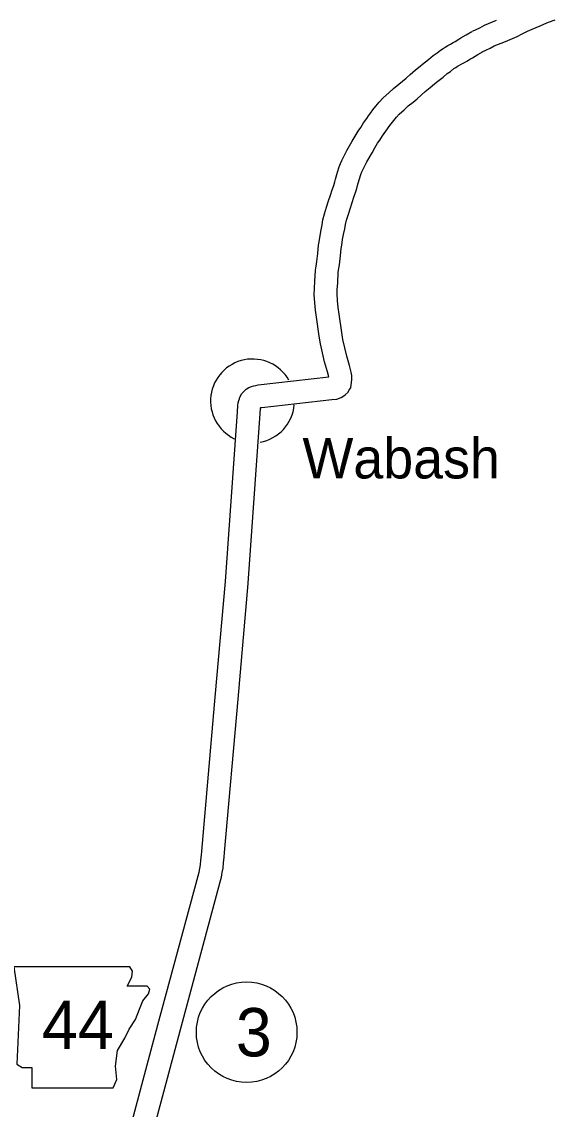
# Model space of a CAD drawing. Extents: x -939622 to -934222, y 1383701 to 1385301.
# Drawn here: x -935804.2 to -935783.2, y 1383947.05 to 1383989.81 of the extents above; entities that cross this region are included whole.
import ezdxf

# ---------------------------------------------------------------- set-up
doc = ezdxf.new("R2010")
doc.units = 0
for name, color, linetype in [('Level 10', 7, 'Continuous'), ('Level 21', 7, 'Continuous'), ('Level 24', 7, 'Continuous'), ('Level 27', 7, 'Continuous')]:
    doc.layers.add(name, color=color, linetype=linetype)

msp = doc.modelspace()

# ---------------------------------------------------------------- linework, layer by layer
at = {"layer": 'Level 10'}
for points in [[(-935786.454, 1383989.444), (-935786.314, 1383989.51), (-935786.172, 1383989.575), (-935785.991, 1383989.674), (-935785.512, 1383989.871)], [(-935786.07, 1383988.63), (-935785.935, 1383988.693), (-935785.767, 1383988.77), (-935785.602, 1383988.861), (-935785.163, 1383989.042), (-935784.702, 1383989.24), (-935784.503, 1383989.334), (-935784.287, 1383989.437), (-935784.111, 1383989.524), (-935783.945, 1383989.587), (-935783.799, 1383989.648), (-935783.644, 1383989.717), (-935783.472, 1383989.792), (-935783.199, 1383989.894)], [(-935796.182, 1383967.795), (-935795.712, 1383974.47), (-935795.698, 1383974.717), (-935795.674, 1383974.831), (-935795.655, 1383974.923), (-935795.631, 1383974.983), (-935795.613, 1383975.051), (-935795.538, 1383975.196), (-935795.456, 1383975.279), (-935795.367, 1383975.371), (-935795.256, 1383975.429), (-935795.151, 1383975.476), (-935795.07, 1383975.492), (-935794.991, 1383975.515), (-935794.889, 1383975.534), (-935792.117, 1383975.851), (-935792.17, 1383976.046), (-935792.282, 1383976.434), (-935792.439, 1383977.144), (-935792.493, 1383977.45), (-935792.595, 1383978.193), (-935792.632, 1383978.476), (-935792.663, 1383978.763), (-935792.69, 1383979.089), (-935792.682, 1383979.317), (-935792.661, 1383979.607), (-935792.638, 1383980.047), (-935792.614, 1383980.197), (-935792.582, 1383980.379), (-935792.551, 1383980.695), (-935792.517, 1383981.024), (-935792.493, 1383981.165), (-935792.459, 1383981.407), (-935792.414, 1383981.631), (-935792.373, 1383981.832), (-935792.343, 1383982.021), (-935792.283, 1383982.261), (-935792.198, 1383982.519), (-935792.123, 1383982.765), (-935792.048, 1383982.996), (-935791.975, 1383983.21), (-935791.919, 1383983.375), (-935791.875, 1383983.519), (-935791.843, 1383983.625), (-935791.821, 1383983.709), (-935791.768, 1383983.892), (-935791.701, 1383984.102), (-935791.648, 1383984.239), (-935791.6, 1383984.358), (-935791.473, 1383984.613), (-935791.404, 1383984.744), (-935791.187, 1383985.118), (-935791.072, 1383985.312), (-935790.953, 1383985.515), (-935790.858, 1383985.654), (-935790.742, 1383985.832), (-935790.618, 1383986.011), (-935790.546, 1383986.12), (-935790.474, 1383986.218), (-935790.374, 1383986.352), (-935790.259, 1383986.496), (-935790.137, 1383986.647), (-935789.976, 1383986.823), (-935789.752, 1383987.023), (-935789.572, 1383987.186), (-935789.363, 1383987.356), (-935789.208, 1383987.48), (-935789.072, 1383987.597), (-935788.913, 1383987.745), (-935788.703, 1383987.921), (-935788.522, 1383988.07), (-935788.425, 1383988.149), (-935788.31, 1383988.232), (-935788.188, 1383988.326), (-935788.004, 1383988.488), (-935787.854, 1383988.588), (-935787.723, 1383988.694), (-935787.615, 1383988.766), (-935787.537, 1383988.82), (-935787.428, 1383988.886), (-935787.32, 1383988.938), (-935787.222, 1383988.994), (-935787.139, 1383989.043), (-935786.997, 1383989.13), (-935786.913, 1383989.178), (-935786.7, 1383989.303), (-935786.488, 1383989.426)], [(-935795.284, 1383967.732), (-935794.814, 1383974.412), (-935794.803, 1383974.598), (-935794.796, 1383974.635), (-935794.782, 1383974.638), (-935794.752, 1383974.644), (-935791.998, 1383974.959), (-935791.798, 1383974.976), (-935791.624, 1383975.032), (-935791.519, 1383975.1), (-935791.464, 1383975.146), (-935791.346, 1383975.251), (-935791.306, 1383975.332), (-935791.244, 1383975.423), (-935791.202, 1383975.742), (-935791.208, 1383975.812), (-935791.209, 1383975.902), (-935791.232, 1383976.028), (-935791.303, 1383976.289), (-935791.409, 1383976.656), (-935791.556, 1383977.32), (-935791.604, 1383977.59), (-935791.703, 1383978.313), (-935791.738, 1383978.582), (-935791.767, 1383978.848), (-935791.789, 1383979.11), (-935791.783, 1383979.268), (-935791.763, 1383979.55), (-935791.741, 1383979.952), (-935791.726, 1383980.049), (-935791.69, 1383980.259), (-935791.656, 1383980.605), (-935791.625, 1383980.902), (-935791.604, 1383981.026), (-935791.572, 1383981.254), (-935791.532, 1383981.453), (-935791.487, 1383981.673), (-935791.461, 1383981.84), (-935791.418, 1383982.01), (-935791.34, 1383982.247), (-935791.265, 1383982.495), (-935791.195, 1383982.711), (-935791.123, 1383982.92), (-935791.062, 1383983.099), (-935791.014, 1383983.257), (-935790.977, 1383983.38), (-935790.953, 1383983.471), (-935790.907, 1383983.632), (-935790.852, 1383983.803), (-935790.812, 1383983.907), (-935790.779, 1383983.987), (-935790.671, 1383984.204), (-935790.616, 1383984.309), (-935790.411, 1383984.662), (-935790.296, 1383984.855), (-935790.191, 1383985.034), (-935790.109, 1383985.155), (-935789.995, 1383985.329), (-935789.872, 1383985.507), (-935789.808, 1383985.605), (-935789.75, 1383985.682), (-935789.661, 1383985.803), (-935789.557, 1383985.932), (-935789.454, 1383986.06), (-935789.343, 1383986.182), (-935789.151, 1383986.354), (-935788.987, 1383986.502), (-935788.798, 1383986.655), (-935788.633, 1383986.787), (-935788.472, 1383986.926), (-935788.316, 1383987.07), (-935788.128, 1383987.229), (-935787.952, 1383987.373), (-935787.877, 1383987.434), (-935787.773, 1383987.51), (-935787.615, 1383987.63), (-935787.454, 1383987.772), (-935787.319, 1383987.862), (-935787.188, 1383987.969), (-935787.112, 1383988.02), (-935787.048, 1383988.064), (-935786.996, 1383988.095), (-935786.901, 1383988.142), (-935786.773, 1383988.215), (-935786.677, 1383988.27), (-935786.539, 1383988.355), (-935786.462, 1383988.399), (-935786.246, 1383988.525), (-935786.036, 1383988.648)], [(-935804.586, 1383930.251), (-935804.322, 1383931.164), (-935802.411, 1383938.033), (-935802.345, 1383938.267), (-935802.303, 1383938.38), (-935802.256, 1383938.476), (-935802.14, 1383938.625), (-935801.955, 1383938.727), (-935801.946, 1383938.73), (-935801.756, 1383939.445), (-935798.837, 1383950.366), (-935797.258, 1383956.223), (-935797.22, 1383956.373), (-935797.191, 1383956.516), (-935797.167, 1383956.654), (-935797.146, 1383956.842), (-935797.123, 1383957.04), (-935797.115, 1383957.202), (-935796.58, 1383963.255), (-935796.181, 1383967.803)], [(-935803.642, 1383930.27), (-935803.392, 1383931.149), (-935801.544, 1383937.791), (-935801.512, 1383937.906), (-935801.32, 1383938.046), (-935801.244, 1383938.136), (-935801.201, 1383938.196), (-935801.118, 1383938.341), (-935800.886, 1383939.212), (-935797.967, 1383950.133), (-935796.387, 1383955.995), (-935796.342, 1383956.173), (-935796.306, 1383956.351), (-935796.276, 1383956.529), (-935796.252, 1383956.74), (-935796.226, 1383956.965), (-935796.217, 1383957.14), (-935795.683, 1383963.176), (-935795.285, 1383967.725)]]:
    msp.add_lwpolyline(points, dxfattribs=at)
at = {"layer": 'Level 21'}
msp.add_lwpolyline([(-935804.513, 1383952.653), (-935804.285, 1383951.131), (-935804.386, 1383948.822), (-935804.183, 1383948.695), (-935803.802, 1383948.695), (-935803.802, 1383947.883), (-935800.605, 1383947.883), (-935800.453, 1383948.213), (-935800.503, 1383948.745), (-935800.427, 1383949.355), (-935800.148, 1383949.837), (-935799.97, 1383950.192), (-935799.717, 1383950.573), (-935799.564, 1383950.979), (-935799.438, 1383951.309), (-935799.209, 1383951.588), (-935799.158, 1383951.765), (-935799.26, 1383951.892), (-935800.047, 1383951.892), (-935799.869, 1383952.247), (-935799.844, 1383952.476), (-935799.949, 1383952.651)], close=True, dxfattribs=at)
at = {"layer": 'Level 24'}
for start, end in [(29.8865, 243.9465), (280.3048, 354.7528)]:
    msp.add_arc((-935795.116, 1383974.899), 1.65, start, end, dxfattribs=at)
at = {"layer": 'Level 27'}
msp.add_circle((-935795.346, 1383950.076), 1.98, dxfattribs=at)

# ---------------------------------------------------------------- texts
at = {"layer": 'Level 21'}
msp.add_text('44', height=1.9008, dxfattribs=at).set_placement((-935803.402, 1383949.419))
at = {"layer": 'Level 24'}
msp.add_text('Wabash', height=1.584, dxfattribs=at).set_placement((-935793.147, 1383971.854))
at = {"layer": 'Level 27'}
msp.add_text('3', height=1.901, dxfattribs=at).set_placement((-935795.771, 1383949.126))

doc.saveas('drawing.dxf')
